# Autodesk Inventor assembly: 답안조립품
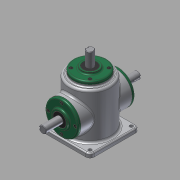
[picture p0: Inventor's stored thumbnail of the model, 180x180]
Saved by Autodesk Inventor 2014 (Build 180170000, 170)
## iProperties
Created: 2015-10
Part Number: 답안조립품
Document SubType Name: Assembly
Designer: Owner
Author: Owner
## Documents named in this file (14)
- C:\Documents and Settings\Owner\바탕 화면\451007V1022\답안조립품.iam
- C:\Documents and Settings\Owner\바탕 화면\451007V1022\1.본체.ipt
- C:\Documents and Settings\Owner\바탕 화면\451007V1022\커버.ipt
- C:\Documents and Settings\Owner\바탕 화면\451007V1022\오일실.ipt
- C:\Documents and Settings\Owner\바탕 화면\451007V1022\베어링 6203.ipt
- C:\Documents and Settings\Owner\바탕 화면\451007V1022\메인 축.ipt
- 메인 축.ipt
- C:\Documents and Settings\Owner\바탕 화면\451007V1022\키 5x5.ipt
- C:\Documents and Settings\Owner\바탕 화면\451007V1022\메인 베벨기어.ipt
- C:\Documents and Settings\Owner\바탕 화면\451007V1022\서브 축.ipt
- 서브 축.ipt
- C:\Documents and Settings\Owner\바탕 화면\451007V1022\키 4x4.ipt
- C:\Documents and Settings\Owner\바탕 화면\451007V1022\서브 베벨기어.ipt
- C:\Documents and Settings\Owner\바탕 화면\451007V1022\M4.ipt
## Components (13 placed, 2 different names)
1. 1.본체:1 — 각도:7, 각도:8, 각도:9
2. M4:1 — 각도:7
3. M4:4
4. M4:5
5. M4:6
6. M4:2 — 각도:8
7. M4:7
8. M4:8
9. M4:9
10. M4:3 — 각도:9
11. M4:10
12. M4:11
13. M4:12
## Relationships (3: Angle 3)
- 각도:7 [Angle]: 1.본체:1 ↔ M4:1
- 각도:8 [Angle]: 1.본체:1 ↔ M4:2
- 각도:9 [Angle]: 1.본체:1 ↔ M4:3
